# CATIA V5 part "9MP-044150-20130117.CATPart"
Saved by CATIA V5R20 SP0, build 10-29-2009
Part number: 9MP-044150-20130117
Revision: ANY
Definition: UNKNOWN
Nomenclature: 9MP-044150-20130117
Source: Unknown
Bounding box of the stored display mesh (mm): x -188.667 to -38.689, y 1552.221 to 1558.675, z 0 to 4
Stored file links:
  C:\Users\Utente\Desktop\IO LAVORO\3D X SITO CF\CUMSA\3D files PF\PF 044150\9MP-044150-20130117.CATPart
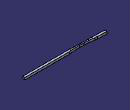
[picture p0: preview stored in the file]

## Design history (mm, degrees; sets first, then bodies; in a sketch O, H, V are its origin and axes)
Body1 "Cortar-Extruir1" (main body)
  Solid1: solid without history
